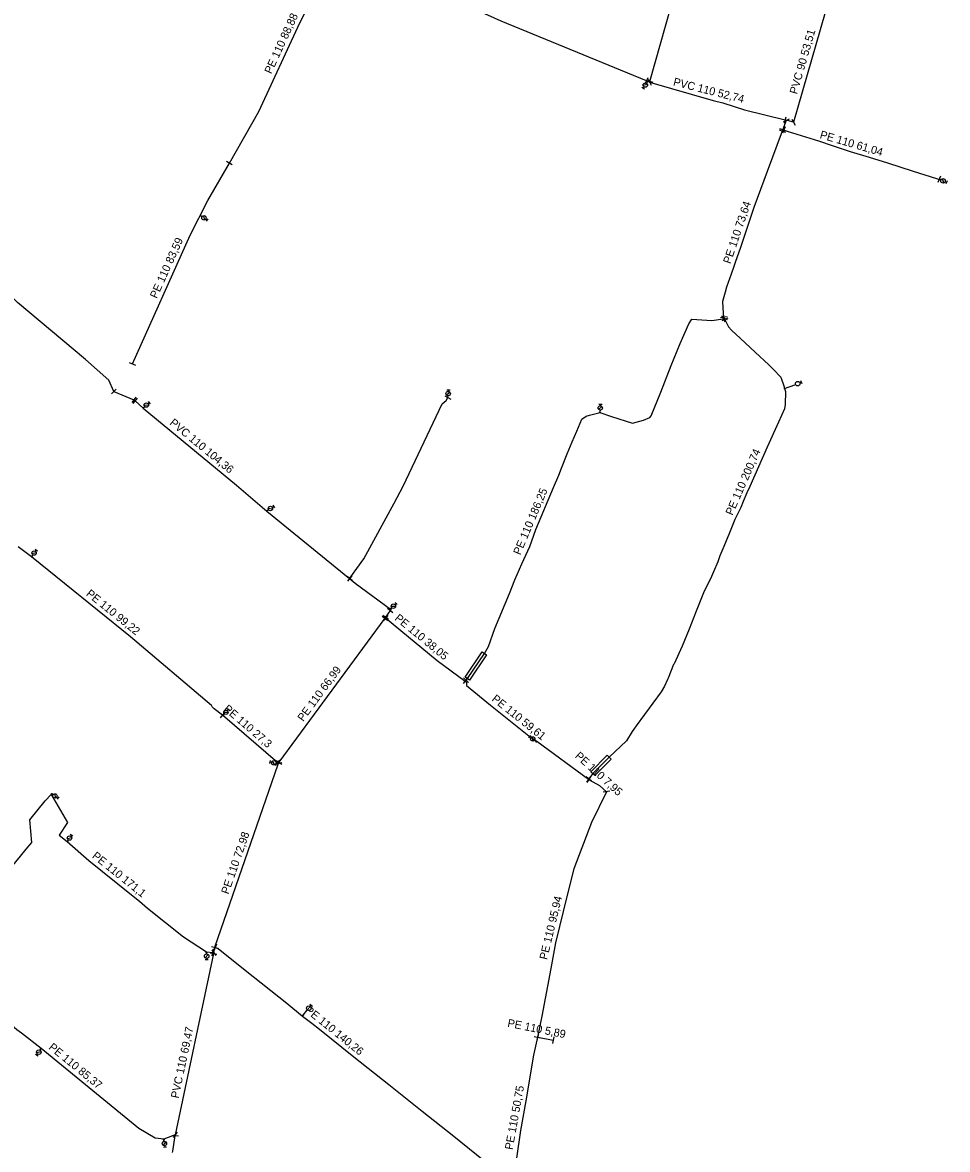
# Model space of a CAD drawing. Extents: x -736619 to -735426, y -1033122 to -1031044.
# Drawn here: x -735849.4 to -735502.8, y -1032713.9 to -1032291.7 of the extents above; entities that cross this region are included whole.
import ezdxf

# ---------------------------------------------------------------- set-up
doc = ezdxf.new("R2010")
doc.units = 0
for name, color, linetype in [('Vrstva 1', 7, 'Continuous'), ('Vrstva 17', 7, 'Continuous'), ('Vrstva 25', 7, 'Continuous'), ('Vrstva 27', 7, 'Continuous'), ('Vrstva 29', 7, 'Continuous'), ('Vrstva 63', 7, 'Continuous')]:
    doc.layers.add(name, color=color, linetype=linetype)

# ---------------------------------------------------------------- blocks, each defined once
blk = doc.blocks.new('100')
at = {"layer": 'Vrstva 1'}
blk.add_circle((0, 0), 0.127, dxfattribs=at)
blk = doc.blocks.new('133')
at = {"layer": 'Vrstva 1'}
for p, q in [((0.28, 0), (0, 0)), ((0.54, 0.58), (1.7, -0.58)), ((1.94, 0), (2.52, 0)), ((2.52, 0.58), (2.52, -0.58))]:
    blk.add_line(p, q, dxfattribs=at)
blk.add_circle((1.105, 0.003), 0.825, dxfattribs=at)
blk = doc.blocks.new('132')
at = {"layer": 'Vrstva 1'}
for p, q in [((0.3, 0), (0, 0)), ((1.96, 0), (2.52, 0)), ((2.52, 0.58), (2.52, -0.58))]:
    blk.add_line(p, q, dxfattribs=at)
blk.add_circle((1.13, -0.006), 0.825, dxfattribs=at)
blk = doc.blocks.new('147')
at = {"layer": 'Vrstva 1'}
blk.add_line((0, 1.27), (0, -1.27), dxfattribs=at)

msp = doc.modelspace()

# ---------------------------------------------------------------- linework, layer by layer
at = {"layer": 'Vrstva 17'}
for p, q in [((-735545.659, -1032277.631), (-735560.511, -1032329.043)), ((-735614.42, -1032314.05), (-735615.597, -1032313.515)), ((-735614.348, -1032313.8), (-735614.42, -1032314.05)), ((-735563.631, -1032328.222), (-735563.2, -1032328.33)), ((-735564.68, -1032332.3), (-735564.52, -1032331.86)), ((-735564.52, -1032331.86), (-735563.2, -1032328.33)), ((-735564.52, -1032331.86), (-735564.12, -1032331.98)), ((-735586.83, -1032402.7), (-735586.51, -1032402.51)), ((-735586.51, -1032402.51), (-735586.6, -1032402.13)), ((-735586.51, -1032402.51), (-735586.28, -1032402.97)), ((-735807.713, -1032433.118), (-735807.225, -1032433.465)), ((-735726.847, -1032500.019), (-735726.787, -1032499.953)), ((-735711.597, -1032511.963), (-735713.35, -1032514.5)), ((-735713.64, -1032514.92), (-735753.328, -1032568.894)), ((-735713.486, -1032514.698), (-735713.64, -1032514.92)), ((-735713.35, -1032514.5), (-735713.486, -1032514.698)), ((-735713.486, -1032514.698), (-735713.37, -1032514.8)), ((-735683.56, -1032538.43), (-735683.23, -1032538.11)), ((-735753.803, -1032569.027), (-735774.512, -1032551.19)), ((-735753.482, -1032569.247), (-735753.328, -1032568.894)), ((-735753.803, -1032569.027), (-735753.482, -1032569.247)), ((-735637.19, -1032575.03), (-735637.364, -1032575.252)), ((-735637.364, -1032575.252), (-735637.135, -1032575.421)), ((-735777.804, -1032640.524), (-735792.194, -1032708.488)), ((-735777.738, -1032640.203), (-735778.071, -1032640.132)), ((-735777.738, -1032640.203), (-735777.804, -1032640.524)), ((-735777.738, -1032640.203), (-735777.373, -1032638.206)), ((-735777.373, -1032638.206), (-735777.177, -1032638.243)), ((-735656.42, -1032671.87), (-735656.352, -1032671.884)), ((-735656.352, -1032671.884), (-735650.583, -1032673.049)), ((-735792.194, -1032708.488), (-735792.19, -1032708.765))]:
    msp.add_line(p, q, dxfattribs=at)
for points in [[(-735614.348, -1032313.8), (-735604.432, -1032278.8), (-735598.389, -1032257.469), (-735590.25, -1032228.773), (-735586.507, -1032218.681)], [(-735615.597, -1032313.515), (-735670.097, -1032291.157), (-735730.177, -1032264.044)], [(-735771.902, -1032344.392), (-735760.828, -1032325.055), (-735745.541, -1032291.769), (-735735.296, -1032271.519), (-735731.407, -1032265.369)], [(-735614.42, -1032314.05), (-735590.56, -1032320.86), (-735587.01, -1032321.76), (-735578.84, -1032324.39), (-735563.636, -1032328.221), (-735563.631, -1032328.222)], [(-735815.232, -1032429.97), (-735817.096, -1032425.726), (-735825.831, -1032417.995), (-735851.243, -1032396.548), (-735857.331, -1032390.732), (-735886.184, -1032366.165), (-735901.653, -1032353.103), (-735923.508, -1032335.433), (-735931.065, -1032329.78), (-735943.091, -1032319.148)], [(-735586.6, -1032402.13), (-735586.87, -1032398.78), (-735586.96, -1032396.05), (-735586.02, -1032392.57), (-735585.47, -1032390.76), (-735584.23, -1032387.21), (-735583.87, -1032386.3), (-735582.57, -1032382.58), (-735582.08, -1032381.14), (-735580.41, -1032376.21), (-735580.17, -1032375.48), (-735575.24, -1032360.83), (-735570.28, -1032347.42), (-735564.68, -1032332.3)], [(-735564.12, -1032331.98), (-735551.21, -1032336.09), (-735545.61, -1032337.87), (-735539.31, -1032340.03), (-735532.21, -1032342.1), (-735525.27, -1032344.27), (-735515.71, -1032347.35), (-735506.993, -1032350.143), (-735505.95, -1032350.46)], [(-735560.511, -1032329.043), (-735562.771, -1032328.444), (-735563.2, -1032328.33)], [(-735808.244, -1032419.601), (-735786.608, -1032371.384), (-735779.94, -1032358.426), (-735771.902, -1032344.392)], [(-735683.23, -1032538.11), (-735682.73, -1032537.5), (-735676.35, -1032528.08), (-735674.84, -1032525.53), (-735672.47, -1032518.79), (-735666.91, -1032505.68), (-735664.93, -1032500.46), (-735662.32, -1032494.56), (-735659.37, -1032488), (-735657.08, -1032481.69), (-735650.44, -1032465.9), (-735648.48, -1032461.31), (-735647.51, -1032458.68), (-735645.32, -1032453.28), (-735643.47, -1032448.81), (-735641.73, -1032444.86), (-735639.78, -1032440.37), (-735638.19, -1032439.2), (-735637.009, -1032438.86), (-735633.45, -1032437.96), (-735633.04, -1032437.85), (-735628.77, -1032439.31), (-735620.84, -1032441.85), (-735616.73, -1032440.74), (-735614.33, -1032439.67), (-735613.89, -1032439.08), (-735610.24, -1032430.16), (-735606.42, -1032420.18), (-735602.99, -1032411.92), (-735599.7, -1032404.59), (-735598.66, -1032402.84), (-735591.07, -1032403.34), (-735586.83, -1032402.7)], [(-735586.28, -1032402.97), (-735584.93, -1032405.76), (-735583.75, -1032406.91), (-735580.42, -1032410.14), (-735574.87, -1032415.17), (-735569.74, -1032419.93), (-735568.13, -1032421.59), (-735565.23, -1032424.56), (-735564.02, -1032428.18), (-735563.852, -1032428.772), (-735563.54, -1032429.93), (-735563.63, -1032434.77), (-735563.95, -1032436.42), (-735566.14, -1032441.39), (-735570.38, -1032450.79), (-735576.84, -1032465.57), (-735577.99, -1032467.86), (-735579.35, -1032471.13), (-735580.28, -1032473.42), (-735582.49, -1032477.96), (-735584.56, -1032482.89), (-735586.62, -1032488.09), (-735588.1, -1032491.5), (-735588.9, -1032493.78), (-735590.5, -1032497.54), (-735591.61, -1032500.08), (-735593.93, -1032504.73), (-735597.05, -1032512.27), (-735599.59, -1032518.96), (-735602.26, -1032525.34), (-735605.26, -1032531.94), (-735605.43, -1032532.29), (-735607.54, -1032537.31), (-735607.78, -1032537.85), (-735608.84, -1032540.34), (-735610.14, -1032542.47), (-735619.494, -1032555.268), (-735620.38, -1032556.53), (-735620.95, -1032557.36), (-735623.06, -1032560.8), (-735629.589, -1032566.959), (-735635.73, -1032573.14), (-735637.19, -1032575.03)], [(-735815.232, -1032429.97), (-735807.721, -1032433.112), (-735807.713, -1032433.118)], [(-735807.225, -1032433.465), (-735804.22, -1032436.189), (-735769.25, -1032465.09), (-735757.856, -1032474.77), (-735726.893, -1032499.981), (-735726.847, -1032500.019)], [(-735726.787, -1032499.953), (-735721.558, -1032492.599), (-735710.114, -1032471.815), (-735706.833, -1032465.454), (-735692.169, -1032434.622), (-735690.679, -1032433.331), (-735690.04, -1032432.197)], [(-735774.512, -1032551.19), (-735777.638, -1032548.821), (-735777.852, -1032548.559), (-735778.305, -1032548.082), (-735778.32, -1032548.066), (-735778.583, -1032547.57), (-735808.91, -1032521.893), (-735846.062, -1032491.872), (-735851.007, -1032488.105)], [(-735726.847, -1032500.019), (-735724.767, -1032501.705), (-735711.557, -1032511.489), (-735711.313, -1032511.636), (-735711.597, -1032511.963)], [(-735713.37, -1032514.8), (-735694, -1032530.73), (-735683.56, -1032538.43)], [(-735683.56, -1032538.43), (-735683.1, -1032538.803), (-735683.1, -1032540.15), (-735674.06, -1032547.45), (-735659.68, -1032558.96), (-735656.73, -1032560.91), (-735637.364, -1032575.252)], [(-735777.373, -1032638.206), (-735753.64, -1032569.572), (-735753.482, -1032569.247)], [(-735637.135, -1032575.421), (-735633.244, -1032577.521), (-735630.63, -1032579.89)], [(-735878.73, -1032648.384), (-735867.528, -1032628.235), (-735861.393, -1032617.508), (-735850.134, -1032604.11), (-735848.028, -1032601.409), (-735845.899, -1032598.884), (-735846.653, -1032590.394), (-735840.929, -1032583.321), (-735838.698, -1032581.01), (-735832.618, -1032591.43), (-735835.683, -1032596.16), (-735832.7, -1032598.584), (-735824.627, -1032605.661), (-735808.597, -1032618.544), (-735805.533, -1032620.875), (-735802.525, -1032623.525), (-735789.126, -1032634.333), (-735780.475, -1032639.942), (-735778.071, -1032640.132)], [(-735630.63, -1032579.89), (-735636.197, -1032591.435), (-735642.77, -1032608.74), (-735645.36, -1032618.7), (-735649.65, -1032636.47), (-735651.51, -1032646.13), (-735654.76, -1032663.95), (-735656.42, -1032671.87)], [(-735777.177, -1032638.243), (-735776.15, -1032638.619), (-735765.929, -1032646.722), (-735750.433, -1032659.11), (-735744.477, -1032663.984), (-735740.953, -1032666.674), (-735738.072, -1032668.896), (-735725.278, -1032679.218), (-735712.204, -1032689.594), (-735699.686, -1032699.643), (-735687.834, -1032709.024), (-735676.655, -1032717.935), (-735665.374, -1032721.804)], [(-735792.194, -1032708.488), (-735796.517, -1032710.028), (-735799.727, -1032709.658), (-735805.839, -1032706.136), (-735823.078, -1032691.959), (-735842.414, -1032676.074), (-735849.814, -1032670.401), (-735851.533, -1032669.102), (-735856.931, -1032664.544), (-735860.343, -1032661.446)], [(-735656.42, -1032671.87), (-735657.93, -1032678.61), (-735660.8, -1032695.69), (-735662.83, -1032706.9), (-735664.36, -1032717.25), (-735665.086, -1032721.865)], [(-735793.16, -1032715.071), (-735793.16, -1032715.07), (-735793.12, -1032714.59), (-735792.19, -1032708.765)]]:
    msp.add_lwpolyline(points, dxfattribs=at)
at = {"layer": 'Vrstva 27'}
for points in [[(-735683.558, -1032536.94), (-735677.178, -1032527.519), (-735675.522, -1032528.641), (-735681.902, -1032538.061), (-735683.558, -1032536.94)], [(-735636.438, -1032572.434), (-735630.298, -1032566.254), (-735628.88, -1032567.664), (-735635.02, -1032573.844), (-735636.438, -1032572.434)]]:
    msp.add_lwpolyline(points, dxfattribs=at)
at = {"layer": 'Vrstva 63'}
for p, q in [((-735505.95, -1032350.46), (-735505.55, -1032350.59)), ((-735782.805, -1032363.993), (-735782.37, -1032364.279)), ((-735563.852, -1032428.772), (-735559.993, -1032427.462)), ((-735690.04, -1032432.197), (-735690.007, -1032431.846)), ((-735633.04, -1032437.85), (-735633, -1032437.22))]:
    msp.add_line(p, q, dxfattribs=at)
for points in [[(-735615.165, -1032313.711), (-735615.268, -1032313.937), (-735615.435, -1032314.202)], [(-735804.22, -1032436.189), (-735804.054, -1032435.988), (-735803.832, -1032435.79)], [(-735757.856, -1032474.77), (-735757.693, -1032474.567), (-735757.445, -1032474.407)], [(-735846.062, -1032491.872), (-735845.896, -1032491.672), (-735845.703, -1032491.396)], [(-735711.557, -1032511.489), (-735711.428, -1032511.319), (-735711.247, -1032511.145)], [(-735774.316, -1032551.359), (-735774.181, -1032551.202), (-735773.934, -1032550.94)], [(-735656.73, -1032560.91), (-735656.88, -1032561.26), (-735657.36, -1032560.85)], [(-735753.64, -1032569.572), (-735753.878, -1032569.365), (-735754.16, -1032569.322)], [(-735838.698, -1032581.01), (-735838.42, -1032580.707), (-735838.178, -1032580.863)], [(-735832.7, -1032598.584), (-735832.57, -1032598.424), (-735832.416, -1032598.187)], [(-735780.475, -1032639.942), (-735780.479, -1032640.159), (-735780.464, -1032640.413)], [(-735744.477, -1032663.984), (-735744.241, -1032663.6), (-735742.843, -1032661.873)], [(-735842.414, -1032676.074), (-735842.58, -1032676.275), (-735842.736, -1032676.548)], [(-735796.517, -1032710.028), (-735796.462, -1032710.285), (-735796.409, -1032710.632)]]:
    msp.add_lwpolyline(points, dxfattribs=at)

# ---------------------------------------------------------------- block references
at = {"layer": 'Vrstva 25'}
for name, p, xscale, yscale, rotation in [('133', (-735615.435, -1032314.202), 0.9999999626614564, 0.9999999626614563, -122.99999840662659), ('133', (-735505.55, -1032350.59), 1.0316957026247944, 1.0316957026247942, -23.584588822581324), ('133', (-735782.37, -1032364.279), 0.9999999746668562, 0.999999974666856, -34.00000045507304), ('133', (-735690.007, -1032431.846), 0.9999999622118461, 0.999999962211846, 85.0000001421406), ('132', (-735559.993, -1032427.462), 1.0316957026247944, 1.0316957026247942, 23.584588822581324), ('133', (-735803.832, -1032435.79), 0.9999999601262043, 0.9999999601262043, 41.999998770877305), ('133', (-735633, -1032437.22), 0.9999999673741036, 0.9999999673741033, 86.00000004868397), ('133', (-735757.445, -1032474.407), 0.9999999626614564, 0.9999999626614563, 32.99999840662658), ('133', (-735845.703, -1032491.396), 0.9999999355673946, 0.9999999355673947, 55.0000006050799), ('133', (-735711.247, -1032511.145), 0.9999999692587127, 0.9999999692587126, 43.999999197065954), ('133', (-735773.934, -1032550.94), 0.9999999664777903, 0.9999999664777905, 47.000001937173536), ('133', (-735657.36, -1032560.85), 0.9999999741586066, 0.9999999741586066, 140.00000129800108), ('133', (-735754.16, -1032569.322), 1.00837761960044, 1.00837761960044, 168.3736213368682), ('133', (-735838.178, -1032580.863), 0.9999999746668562, 0.999999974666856, -34.00000045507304), ('133', (-735832.416, -1032598.187), 0.9999999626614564, 0.9999999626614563, 57.00000159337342), ('133', (-735780.464, -1032640.413), 0.9999999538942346, 0.9999999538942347, -87.9999999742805), ('132', (-735742.843, -1032661.873), 0.9999999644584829, 0.999999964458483, 50.999998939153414), ('133', (-735842.736, -1032676.548), 0.9999999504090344, 0.9999999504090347, -121.00000158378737), ('133', (-735796.409, -1032710.632), 0.9999999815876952, 0.9999999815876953, -82.0000004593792)]:
    msp.add_blockref(name, p, dxfattribs=dict(at, xscale=xscale, yscale=yscale, rotation=rotation))
at = {"layer": 'Vrstva 29'}
for p, xscale, yscale, rotation in [((-735615.597, -1032313.515), 1.022584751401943, 1.022584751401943, 154.18102569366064), ((-735614.348, -1032313.8), 0.9999999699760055, 0.9999999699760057, -106.99999966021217), ((-735614.42, -1032314.05), 1.0169561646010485, 1.0169561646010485, 26.97601647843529), ((-735563.2, -1032328.33), 0.9999999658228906, 0.9999999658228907, 117.99999982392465), ((-735563.631, -1032328.222), 1.0009847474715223, 1.0009847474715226, 165.7756737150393), ((-735560.511, -1032329.043), 0.9999999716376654, 0.9999999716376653, 29.999998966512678), ((-735564.68, -1032332.3), 0.9999999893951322, 0.9999999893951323, 70.00000094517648), ((-735564.52, -1032331.86), 0.9999999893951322, 0.9999999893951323, 70.00000094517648), ((-735564.12, -1032331.98), 1.0335064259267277, 1.033506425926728, -23.04128150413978), ((-735771.902, -1032344.392), 0.9999999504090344, 0.9999999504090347, -121.00000158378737), ((-735505.95, -1032350.46), 1.0335064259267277, 1.033506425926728, -23.04128150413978), ((-735586.6, -1032402.13), 0.9999999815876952, 0.9999999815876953, -82.0000004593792), ((-735586.51, -1032402.51), 0.9999999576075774, 0.9999999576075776, 66.99999911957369), ((-735586.28, -1032402.97), 0.9999999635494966, 0.9999999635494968, -65.00000039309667), ((-735586.83, -1032402.7), 1.0296949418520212, 1.0296949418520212, 24.133789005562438), ((-735808.244, -1032419.601), 0.9999999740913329, 0.9999999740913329, 65.99999939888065), ((-735815.232, -1032429.97), 0.999999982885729, 0.9999999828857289, -45), ((-735807.713, -1032433.118), 0.9999999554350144, 0.9999999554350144, -36.99999920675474), ((-735807.225, -1032433.465), 0.9999999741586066, 0.9999999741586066, -39.999998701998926), ((-735690.04, -1032432.197), 0.999999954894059, 0.9999999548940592, 60.999999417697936), ((-735726.787, -1032499.953), 0.9999999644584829, 0.999999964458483, 50.999998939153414), ((-735726.847, -1032500.019), 0.9999999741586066, 0.9999999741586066, -39.999998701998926), ((-735713.486, -1032514.698), 0.9999999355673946, 0.9999999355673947, 55.0000006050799), ((-735713.35, -1032514.5), 0.9999999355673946, 0.9999999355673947, 55.0000006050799), ((-735713.37, -1032514.8), 0.9999999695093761, 0.9999999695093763, -41.000001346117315), ((-735711.597, -1032511.963), 0.9999999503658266, 0.9999999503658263, 52.00000018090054), ((-735713.64, -1032514.92), 0.9999999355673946, 0.9999999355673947, 55.0000006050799), ((-735683.56, -1032538.43), 0.9999999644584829, 0.999999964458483, -39.000001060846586), ((-735683.23, -1032538.11), 0.9999999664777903, 0.9999999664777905, 47.000001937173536), ((-735774.512, -1032551.19), 0.9999999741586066, 0.9999999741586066, -39.999998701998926), ((-735753.482, -1032569.247), 0.999999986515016, 0.9999999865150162, 105.00000012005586), ((-735753.803, -1032569.027), 0.9999999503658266, 0.9999999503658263, 142.00000018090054), ((-735753.328, -1032568.894), 0.9999999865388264, 0.9999999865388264, 59.99999955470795), ((-735637.19, -1032575.03), 0.9999999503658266, 0.9999999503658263, 52.00000018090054), ((-735637.364, -1032575.252), 0.9999999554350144, 0.9999999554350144, -36.99999920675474), ((-735637.135, -1032575.421), 0.9999999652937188, 0.9999999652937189, 148.0000026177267), ((-735630.63, -1032579.89), 0.9999999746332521, 0.9999999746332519, -80.00000055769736), ((-735777.804, -1032640.524), 0.999999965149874, 0.9999999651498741, 77.9999999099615), ((-735777.373, -1032638.206), 0.999999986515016, 0.9999999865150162, 74.99999987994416), ((-735777.738, -1032640.203), 0.9999999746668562, 0.999999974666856, 34.00000045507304), ((-735778.071, -1032640.132), 1.0092050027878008, 1.0092050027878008, 168.88308178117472), ((-735777.177, -1032638.243), 1.0365458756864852, 1.0365458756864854, -21.97149085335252), ((-735656.42, -1032671.87), 0.999999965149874, 0.9999999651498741, 77.9999999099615), ((-735656.352, -1032671.884), 1.0045862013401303, 1.00458620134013, -13.17409066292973), ((-735650.583, -1032673.049), 1.0045862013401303, 1.00458620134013, -13.17409066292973), ((-735792.194, -1032708.488), 0.9999999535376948, 0.9999999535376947, -36.000001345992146), ((-735792.19, -1032708.765), 0.9999999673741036, 0.9999999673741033, 86.00000004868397)]:
    msp.add_blockref('147', p, dxfattribs=dict(at, xscale=xscale, yscale=yscale, rotation=rotation))
at = {"layer": 'Vrstva 63'}
for p, xscale, yscale, rotation in [((-735615.268, -1032313.937), 0.9999999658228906, 0.9999999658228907, 62.00000017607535), ((-735782.674, -1032364.079), 0.9999999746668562, 0.999999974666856, -34.00000045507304), ((-735563.85, -1032428.771), 1.0316957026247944, 1.0316957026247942, 23.584588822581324), ((-735563.81, -1032428.758), 1.0316957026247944, 1.0316957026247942, 23.584588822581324), ((-735804.054, -1032435.988), 0.9999999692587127, 0.9999999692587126, 46.00000080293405), ((-735633.039, -1032437.829), 0.9999999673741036, 0.9999999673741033, 86.00000004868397), ((-735757.691, -1032474.566), 0.9999999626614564, 0.9999999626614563, 32.99999840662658), ((-735845.896, -1032491.672), 0.9999999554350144, 0.9999999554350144, 53.00000079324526), ((-735711.428, -1032511.319), 0.9999999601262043, 0.9999999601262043, 48.0000012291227), ((-735774.181, -1032551.202), 0.9999999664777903, 0.9999999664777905, 47.000001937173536), ((-735656.879, -1032561.259), 0.9999999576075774, 0.9999999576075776, 66.99999911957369), ((-735753.883, -1032569.364), 1.0073309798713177, 1.007330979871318, -12.138907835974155), ((-735838.42, -1032580.707), 1.0098116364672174, 1.0098116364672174, 10.610300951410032), ((-735832.57, -1032598.424), 0.9999999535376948, 0.9999999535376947, 53.99999865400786), ((-735744.241, -1032663.6), 0.9999999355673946, 0.9999999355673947, 55.0000006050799), ((-735842.58, -1032676.275), 0.9999999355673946, 0.9999999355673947, 55.0000006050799), ((-735796.462, -1032710.285), 0.9999999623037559, 0.999999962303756, -80.99999986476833)]:
    msp.add_blockref('100', p, dxfattribs=dict(at, xscale=xscale, yscale=yscale, rotation=rotation))
at = {"layer": 'Vrstva 63', "rotation": -90}
msp.add_blockref('100', (-735780.479, -1032640.159), dxfattribs=at)

# ---------------------------------------------------------------- texts
at = {"layer": 'Vrstva 63'}
for s, rotation, p in [('PE 110 88,88', 65.33, (-735756.215, -1032311.177)), ('PVC 90 53,51', 73.89, (-735559.207, -1032318.77)), ('PVC 110 52,74', 345.77, (-735605.799, -1032315.217)), ('PE 110 61,04', 343.75, (-735550.87, -1032334.993)), ('PE 110 73,64', 71.4, (-735584.163, -1032382.329)), ('PE 110 83,59', 65.83, (-735799.106, -1032395.327)), ('PVC 110 104,36', 320.43, (-735794.538, -1032442.114)), ('PE 110 200,74', 66.39, (-735583.399, -1032476.583)), ('PE 110 186,25', 67.19, (-735662.909, -1032491.424)), ('PE 110 99,22', 321.06, (-735825.82, -1032506.171)), ('PE 110 38,05', 320.57, (-735710.194, -1032515.341)), ('PE 110 66,99', 53.67, (-735744.235, -1032553.826)), ('PE 110 59,61', 321.33, (-735673.821, -1032545.593)), ('PE 110 27,3', 319.26, (-735774.289, -1032549.268)), ('PE 110 7,95', 317.81, (-735642.625, -1032566.858)), ('PE 110 72,98', 70.93, (-735772.259, -1032618.526)), ('PE 110 171,1', 321.21, (-735823.594, -1032604.437)), ('PE 110 95,94', 76.43, (-735652.883, -1032643.046)), ('PE 110 140,26', 321.1, (-735743.794, -1032662.221)), ('PE 110 5,89', 348.58, (-735667.875, -1032667.923)), ('PVC 110 69,47', 78.05, (-735790.966, -1032694.972)), ('PE 110 85,37', 320.6, (-735839.871, -1032676.092)), ('PE 110 50,75', 79.74, (-735665.783, -1032714.238))]:
    msp.add_text(s, height=2.99999, rotation=rotation, dxfattribs=at).set_placement(p)

doc.saveas('drawing.dxf')
